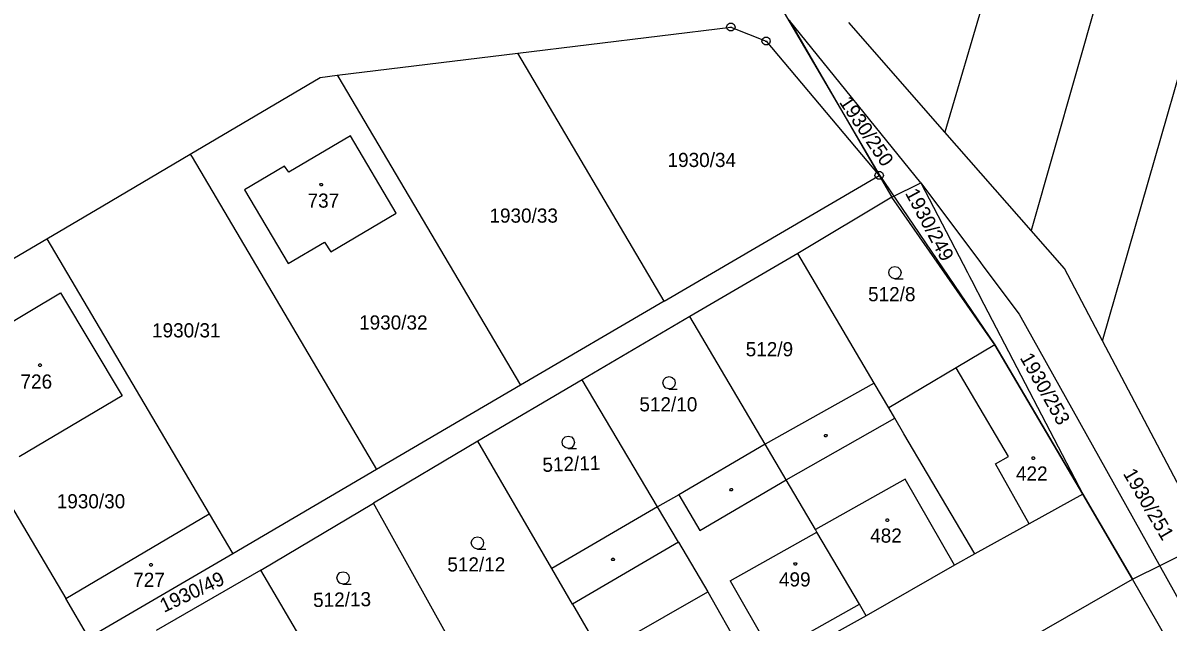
# Model space of a CAD drawing. Extents: x -580630 to -576196, y -1189024 to -1183567.
# Drawn here: x -578746.6 to -578609.3, y -1185295.3 to -1185223.4 of the extents above; entities that cross this region are included whole.
import ezdxf

# ---------------------------------------------------------------- set-up
doc = ezdxf.new("R2010")
doc.units = 0
for name, color, linetype in [('Vrstva 1', 7, 'Continuous'), ('Vrstva 18', 7, 'Continuous'), ('Vrstva 19', 7, 'Continuous'), ('Vrstva 24', 7, 'Continuous'), ('Vrstva 25', 7, 'Continuous'), ('Vrstva 4', 7, 'Continuous'), ('Vrstva 6', 7, 'Continuous'), ('Vrstva 63', 7, 'Continuous')]:
    doc.layers.add(name, color=color, linetype=linetype)

msp = doc.modelspace()

# ---------------------------------------------------------------- linework, layer by layer
at = {"layer": 'Vrstva 1'}
for p, q in [((-578687.25, -1185227.03), (-578661.71, -1185223.9)), ((-578661.71, -1185223.9), (-578657.48, -1185225.58)), ((-578654.73, -1185223.05), (-578643.91, -1185241.7)), ((-578657.48, -1185225.58), (-578643.91, -1185241.7)), ((-578708.92, -1185229.68), (-578687.25, -1185227.03)), ((-578669.69, -1185256.79), (-578687.25, -1185227.03)), ((-578710.98, -1185229.93), (-578708.92, -1185229.68)), ((-578708.92, -1185229.68), (-578708.85, -1185229.79)), ((-578726.56, -1185239.14), (-578710.98, -1185229.93)), ((-578708.85, -1185229.79), (-578686.94, -1185266.89)), ((-578707.33, -1185236.93), (-578714.74, -1185241.32)), ((-578701.85, -1185246.23), (-578707.33, -1185236.93)), ((-578737.07, -1185245.34), (-578726.56, -1185239.14)), ((-578726.56, -1185239.14), (-578726.35, -1185239.5)), ((-578726.35, -1185239.5), (-578704.2, -1185276.99)), ((-578715.24, -1185240.57), (-578720.05, -1185243.43)), ((-578714.74, -1185241.32), (-578715.24, -1185240.57)), ((-578669.69, -1185256.79), (-578643.91, -1185241.7)), ((-578643.91, -1185241.7), (-578642.41, -1185244.3)), ((-578720.05, -1185243.43), (-578714.82, -1185252.26)), ((-578642.41, -1185244.3), (-578653.69, -1185251.09)), ((-578630.02, -1185262.03), (-578642.41, -1185244.3)), ((-578743.78, -1185249.3), (-578737.07, -1185245.34)), ((-578709.71, -1185250.88), (-578701.85, -1185246.23)), ((-578761.01, -1185259.48), (-578743.78, -1185249.3)), ((-578743.78, -1185249.3), (-578724.3, -1185282.31)), ((-578714.82, -1185252.26), (-578710.44, -1185249.69)), ((-578710.44, -1185249.69), (-578709.71, -1185250.88)), ((-578653.69, -1185251.09), (-578666.63, -1185258.63)), ((-578644.53, -1185266.63), (-578653.69, -1185251.09)), ((-578754.43, -1185263.14), (-578742.11, -1185255.79)), ((-578742.11, -1185255.79), (-578734.74, -1185268.14)), ((-578669.69, -1185256.79), (-578686.94, -1185266.89)), ((-578761.01, -1185259.48), (-578741.49, -1185292.5)), ((-578666.63, -1185258.63), (-578679.55, -1185266.24)), ((-578657.59, -1185273.95), (-578666.63, -1185258.63)), ((-578630.02, -1185262.03), (-578634.67, -1185264.79)), ((-578619.47, -1185279.96), (-578630.02, -1185262.03)), ((-578634.67, -1185264.79), (-578642.77, -1185269.61)), ((-578679.55, -1185266.24), (-578692.05, -1185273.58)), ((-578670.52, -1185281.46), (-578679.55, -1185266.24)), ((-578644.53, -1185266.63), (-578657.59, -1185273.95)), ((-578642.77, -1185269.61), (-578644.53, -1185266.63)), ((-578734.74, -1185268.14), (-578747.08, -1185275.48)), ((-578686.94, -1185266.89), (-578704.2, -1185276.99)), ((-578642.04, -1185270.85), (-578642.77, -1185269.61)), ((-578640.94, -1185272.71), (-578642.04, -1185270.85)), ((-578692.05, -1185273.58), (-578704.59, -1185281.04)), ((-578683.18, -1185288.89), (-578692.05, -1185273.58)), ((-578632.44, -1185287.13), (-578640.94, -1185272.71)), ((-578657.59, -1185273.95), (-578667.94, -1185280.04)), ((-578655.08, -1185278.22), (-578657.59, -1185273.95)), ((-578704.2, -1185276.99), (-578721.47, -1185287.1)), ((-578651.56, -1185284.2), (-578655.08, -1185278.22)), ((-578667.94, -1185280.04), (-578670.52, -1185281.46)), ((-578619.47, -1185279.96), (-578625.9, -1185283.52)), ((-578613.51, -1185290.17), (-578619.47, -1185279.96)), ((-578718.1, -1185289.1), (-578704.59, -1185281.04)), ((-578695.74, -1185296.94), (-578704.59, -1185281.04)), ((-578670.52, -1185281.46), (-578683.18, -1185288.89)), ((-578668, -1185285.71), (-578670.52, -1185281.46)), ((-578741.49, -1185292.5), (-578724.3, -1185282.31)), ((-578724.3, -1185282.31), (-578721.47, -1185287.1)), ((-578651.38, -1185284.51), (-578651.56, -1185284.2)), ((-578646.28, -1185293.17), (-578651.38, -1185284.51)), ((-578625.9, -1185283.52), (-578632.44, -1185287.13)), ((-578668, -1185285.71), (-578664.48, -1185291.7)), ((-578721.47, -1185287.1), (-578738.72, -1185297.19)), ((-578632.44, -1185287.13), (-578634.89, -1185288.48)), ((-578634.89, -1185288.48), (-578645.47, -1185294.55)), ((-578718.1, -1185289.1), (-578730.65, -1185296.32)), ((-578709.51, -1185303.62), (-578718.1, -1185289.1)), ((-578680.7, -1185293.18), (-578683.18, -1185288.89)), ((-578626.54, -1185297.65), (-578613.51, -1185290.17)), ((-578609.38, -1185297.4), (-578613.51, -1185290.17)), ((-578738.72, -1185297.19), (-578741.49, -1185292.5)), ((-578664.48, -1185291.7), (-578659.42, -1185300.56)), ((-578680.7, -1185293.18), (-578677.04, -1185299.49)), ((-578645.47, -1185294.55), (-578646.28, -1185293.17)), ((-578645.47, -1185294.55), (-578651.88, -1185298.14))]:
    msp.add_line(p, q, dxfattribs=at)
at = {"layer": 'Vrstva 24'}
for p, q in [((-578661.83, -1185223.9), (-578661.59, -1185223.9)), ((-578657.6, -1185225.58), (-578657.36, -1185225.58)), ((-578644.03, -1185241.7), (-578643.79, -1185241.7))]:
    msp.add_line(p, q, dxfattribs=at)
for points in [[(-578661.56, -1185223.42), (-578661.31, -1185223.6), (-578661.21, -1185223.89), (-578661.31, -1185224.18), (-578661.56, -1185224.36), (-578661.87, -1185224.36), (-578662.12, -1185224.18), (-578662.22, -1185223.89), (-578662.12, -1185223.6), (-578661.87, -1185223.42)], [(-578657.33, -1185225.1), (-578657.08, -1185225.28), (-578656.98, -1185225.57), (-578657.08, -1185225.86), (-578657.33, -1185226.04), (-578657.64, -1185226.04), (-578657.89, -1185225.86), (-578657.99, -1185225.57), (-578657.89, -1185225.28), (-578657.64, -1185225.1)], [(-578643.76, -1185241.22), (-578643.51, -1185241.4), (-578643.41, -1185241.69), (-578643.51, -1185241.98), (-578643.76, -1185242.16), (-578644.07, -1185242.16), (-578644.32, -1185241.98), (-578644.42, -1185241.69), (-578644.32, -1185241.4), (-578644.07, -1185241.22)]]:
    msp.add_lwpolyline(points, close=True, dxfattribs=at)
at = {"layer": 'Vrstva 25'}
for points in [[(-578710.76, -1185242.65), (-578710.67, -1185242.8), (-578710.76, -1185242.95), (-578710.94, -1185242.95), (-578711.03, -1185242.8), (-578710.94, -1185242.65)], [(-578744.49, -1185264.32), (-578744.4, -1185264.47), (-578744.49, -1185264.62), (-578744.67, -1185264.62), (-578744.76, -1185264.47), (-578744.67, -1185264.32)], [(-578650.23, -1185272.78), (-578650.14, -1185272.93), (-578650.23, -1185273.08), (-578650.41, -1185273.08), (-578650.5, -1185272.93), (-578650.41, -1185272.78)], [(-578625.31, -1185275.48), (-578625.22, -1185275.63), (-578625.31, -1185275.78), (-578625.49, -1185275.78), (-578625.58, -1185275.63), (-578625.49, -1185275.48)], [(-578661.58, -1185279.27), (-578661.49, -1185279.42), (-578661.58, -1185279.57), (-578661.76, -1185279.57), (-578661.85, -1185279.42), (-578661.76, -1185279.27)], [(-578642.85, -1185282.93), (-578642.76, -1185283.08), (-578642.85, -1185283.23), (-578643.03, -1185283.23), (-578643.12, -1185283.08), (-578643.03, -1185282.93)], [(-578731.19, -1185288.29), (-578731.1, -1185288.44), (-578731.19, -1185288.59), (-578731.37, -1185288.59), (-578731.46, -1185288.44), (-578731.37, -1185288.29)], [(-578675.76, -1185287.64), (-578675.67, -1185287.79), (-578675.76, -1185287.94), (-578675.94, -1185287.94), (-578676.03, -1185287.79), (-578675.94, -1185287.64)], [(-578653.89, -1185288.19), (-578653.8, -1185288.34), (-578653.89, -1185288.49), (-578654.07, -1185288.49), (-578654.16, -1185288.34), (-578654.07, -1185288.19)]]:
    msp.add_lwpolyline(points, close=True, dxfattribs=at)
for points in [[(-578642.02, -1185254.1), (-578642.4, -1185254), (-578642.67, -1185253.73), (-578642.77, -1185253.36), (-578642.67, -1185252.99), (-578642.4, -1185252.72), (-578642.03, -1185252.62), (-578641.66, -1185252.72), (-578641.39, -1185252.99), (-578641.29, -1185253.37), (-578641.39, -1185253.75), (-578641.66, -1185254.02), (-578642.04, -1185254.12), (-578641.04, -1185254.12)], [(-578669.11, -1185267.32), (-578669.49, -1185267.22), (-578669.76, -1185266.95), (-578669.86, -1185266.58), (-578669.76, -1185266.21), (-578669.49, -1185265.94), (-578669.12, -1185265.84), (-578668.75, -1185265.94), (-578668.48, -1185266.21), (-578668.38, -1185266.59), (-578668.48, -1185266.97), (-578668.75, -1185267.24), (-578669.13, -1185267.34), (-578668.13, -1185267.34)], [(-578681.2, -1185274.47), (-578681.58, -1185274.37), (-578681.85, -1185274.1), (-578681.95, -1185273.73), (-578681.85, -1185273.36), (-578681.58, -1185273.09), (-578681.21, -1185272.99), (-578680.84, -1185273.09), (-578680.57, -1185273.36), (-578680.47, -1185273.74), (-578680.57, -1185274.12), (-578680.84, -1185274.39), (-578681.22, -1185274.49), (-578680.22, -1185274.49)], [(-578692.1, -1185286.54), (-578692.48, -1185286.44), (-578692.75, -1185286.17), (-578692.85, -1185285.8), (-578692.75, -1185285.43), (-578692.48, -1185285.16), (-578692.11, -1185285.06), (-578691.74, -1185285.16), (-578691.47, -1185285.43), (-578691.37, -1185285.81), (-578691.47, -1185286.19), (-578691.74, -1185286.46), (-578692.12, -1185286.56), (-578691.12, -1185286.56)], [(-578708.22, -1185290.75), (-578708.6, -1185290.65), (-578708.87, -1185290.38), (-578708.97, -1185290.01), (-578708.87, -1185289.64), (-578708.6, -1185289.37), (-578708.23, -1185289.27), (-578707.86, -1185289.37), (-578707.59, -1185289.64), (-578707.49, -1185290.02), (-578707.59, -1185290.4), (-578707.86, -1185290.67), (-578708.24, -1185290.77), (-578707.24, -1185290.77)]]:
    msp.add_lwpolyline(points, dxfattribs=at)
at = {"layer": 'Vrstva 4'}
for p, q in [((-578632.82, -1185267.93), (-578634.67, -1185264.79)), ((-578628.4, -1185275.44), (-578632.82, -1185267.93)), ((-578655.08, -1185278.22), (-578642.04, -1185270.85)), ((-578629.95, -1185276.31), (-578628.4, -1185275.44)), ((-578625.9, -1185283.52), (-578629.95, -1185276.31)), ((-578665.42, -1185284.31), (-578655.08, -1185278.22)), ((-578640.79, -1185278.16), (-578651.56, -1185284.2)), ((-578634.89, -1185288.48), (-578640.79, -1185278.16)), ((-578667.94, -1185280.04), (-578665.42, -1185284.31)), ((-578661.8, -1185290.35), (-578651.38, -1185284.51)), ((-578668, -1185285.71), (-578680.7, -1185293.18)), ((-578661.8, -1185290.35), (-578656.01, -1185300.46)), ((-578674.93, -1185297.67), (-578664.48, -1185291.7)), ((-578652.66, -1185296.75), (-578646.28, -1185293.17))]:
    msp.add_line(p, q, dxfattribs=at)
at = {"layer": 'Vrstva 6'}
for p, q in [((-578610.05, -1185148.16), (-578636.04, -1185236.5)), ((-578598.49, -1185152.83), (-578625.69, -1185248.3)), ((-578617.11, -1185261.55), (-578588.13, -1185160.55)), ((-578638.93, -1185242.59), (-578654.73, -1185223.05)), ((-578636.04, -1185236.5), (-578647.57, -1185223.36)), ((-578625.69, -1185248.3), (-578636.04, -1185236.5)), ((-578642.41, -1185244.3), (-578638.93, -1185242.59)), ((-578638.93, -1185242.59), (-578631.77, -1185252.14)), ((-578638.93, -1185242.59), (-578633.32, -1185253.37)), ((-578621.67, -1185252.88), (-578625.69, -1185248.3)), ((-578631.77, -1185252.14), (-578631.47, -1185252.54)), ((-578631.47, -1185252.54), (-578627.1, -1185258.36)), ((-578617.11, -1185261.55), (-578621.67, -1185252.88)), ((-578633.32, -1185253.37), (-578633.08, -1185253.83)), ((-578633.08, -1185253.83), (-578632.84, -1185254.29)), ((-578632.84, -1185254.29), (-578631.35, -1185257.15)), ((-578631.35, -1185257.15), (-578619.47, -1185279.96)), ((-578627.1, -1185258.36), (-578590.9, -1185323.31)), ((-578607.81, -1185279.25), (-578617.11, -1185261.55))]:
    msp.add_line(p, q, dxfattribs=at)
at = {"layer": 'Vrstva 63'}
for p, q in [((-578660.97, -1185212.55), (-578643.942, -1185241.53)), ((-578643.942, -1185241.53), (-578630.02, -1185262.03)), ((-578630.02, -1185262.03), (-578619.47, -1185279.96)), ((-578619.47, -1185279.96), (-578613.51, -1185290.17)), ((-578613.51, -1185290.17), (-578604.8, -1185285.81))]:
    msp.add_line(p, q, dxfattribs=at)

# ---------------------------------------------------------------- texts
at = {"layer": 'Vrstva 18'}
for s, rotation, p in [('1930/250', 303.83952, (-578648.765, -1185232.913)), ('1930/249', 298.22453, (-578640.846, -1185243.815)), ('1930/253', 299.54234, (-578627.079, -1185263.587)), ('512/11', 2.23454, (-578684.286, -1185277.295)), ('1930/251', 300.40177, (-578614.71, -1185277.484)), ('1930/49', 25.32473, (-578729.708, -1185294.208)), ('512/13', 0.91673, (-578711.814, -1185293.508))]:
    msp.add_text(s, height=1.7, rotation=rotation, dxfattribs=at).set_placement(p)
for s, p in [('1930/34', (-578669.305, -1185240.69)), ('1930/33', (-578690.672, -1185247.37)), ('512/8', (-578645.246, -1185256.8)), ('1930/32', (-578706.308, -1185260.2)), ('1930/31', (-578731.147, -1185261.14)), ('512/9', (-578659.926, -1185263.41)), ('512/10', (-578672.684, -1185270.02)), ('1930/30', (-578742.581, -1185281.66)), ('512/12', (-578695.721, -1185289.24))]:
    msp.add_text(s, height=1.7, dxfattribs=at).set_placement(p)
at = {"layer": 'Vrstva 19'}
for s, p in [('737', (-578712.491, -1185245.57)), ('726', (-578746.928, -1185267.29)), ('422', (-578627.501, -1185278.33)), ('482', (-578644.995, -1185285.78)), ('727', (-578733.407, -1185291.09)), ('499', (-578655.934, -1185291.04))]:
    msp.add_text(s, height=1.7, dxfattribs=at).set_placement(p)

doc.saveas('drawing.dxf')
